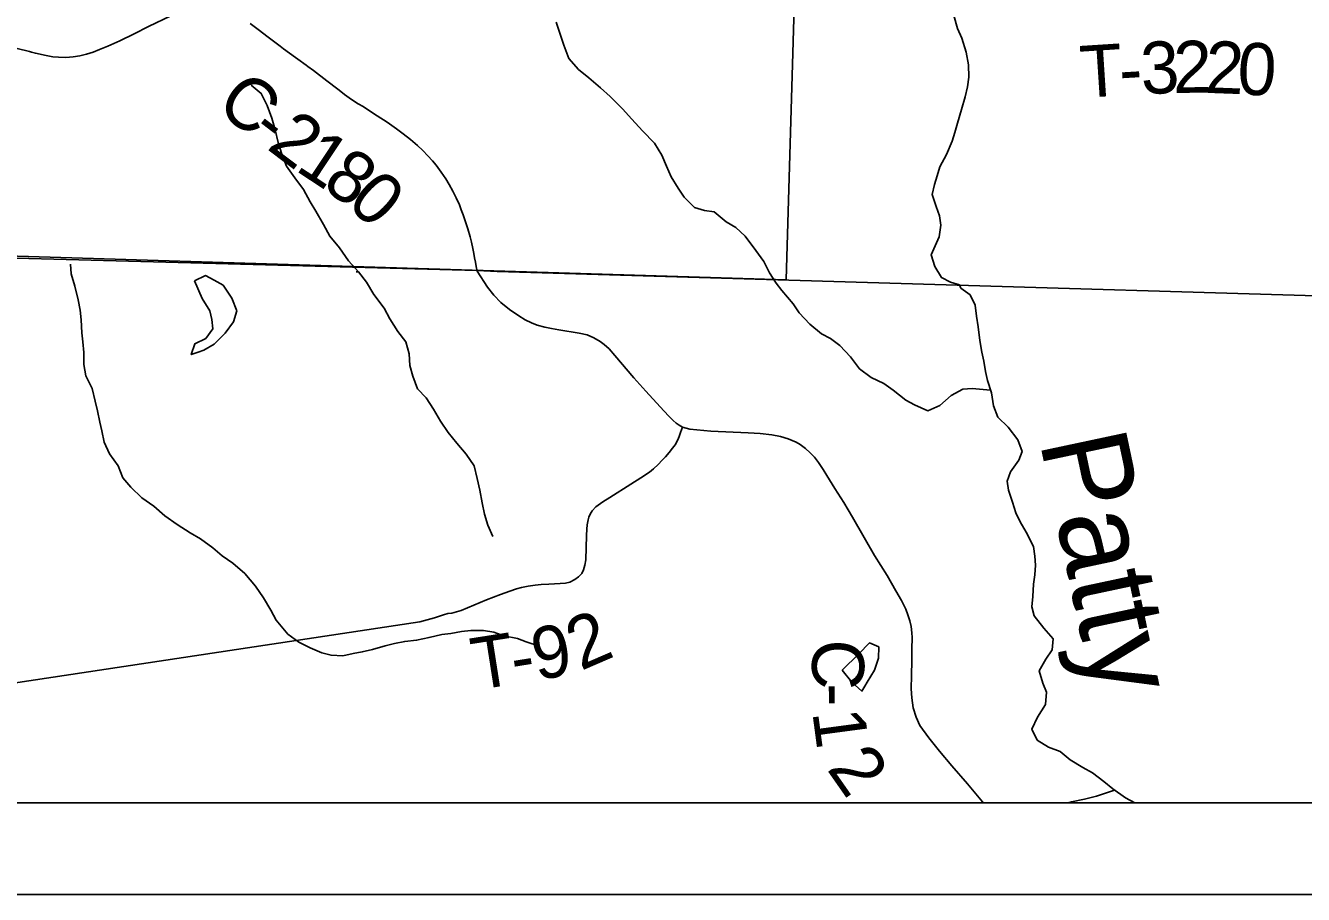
# Model space of a CAD drawing. Extents: x 0 to 34, y 0 to 22.
# Drawn here: x 24.166 to 25.56, y 14 to 14.948 of the extents above; entities that cross this region are included whole.
import ezdxf

# ---------------------------------------------------------------- set-up
doc = ezdxf.new("R2010")
doc.units = 0
for name, color, linetype in [('GM_X_Corporation', 7, 'Continuous'), ('GM_X_County_Road', 7, 'Continuous'), ('GM_X_County_Road_Text', 7, 'Continuous'), ('GM_X_Minor_Lake', 7, 'Continuous'), ('GM_X_Minor_River', 7, 'Continuous'), ('GM_X_Minor_River_Text', 7, 'Continuous'), ('GM_X_Township_Road', 7, 'Continuous'), ('GM_X_Township_Road_Text', 7, 'Continuous'), ('SH_Data', 7, 'Continuous')]:
    doc.layers.add(name, color=color, linetype=linetype)

msp = doc.modelspace()

# ---------------------------------------------------------------- linework, layer by layer
at = {"layer": 'GM_X_Corporation'}
for points in [[(30.3167, 20.9), (23.5167, 20.9), (23.5167, 14.7114), (24.6586, 14.6808), (24.6805, 14.6799), (26.0522, 14.6391), (26.4447, 14.6283), (26.4468, 14.6272), (26.4498, 14.6263), (26.4544, 14.6257), (26.5226, 14.6248), (26.5325, 14.6248), (26.5616, 14.6241), (26.5684, 14.624), (26.5727, 14.624), (26.5813, 14.6239), (26.5991, 14.6234), (26.6128, 14.6229), (26.6208, 14.6225), (26.6337, 14.622), (26.643, 14.6216), (26.6535, 14.621), (27.01, 14.6164)], [(23.5167, 20.7862), (23.5167, 14.7114), (24.6586, 14.6808), (24.6805, 14.6799), (26.0522, 14.6391), (26.4447, 14.6283), (26.4468, 14.6272), (26.4498, 14.6263), (26.4544, 14.6257), (26.5226, 14.6248), (26.5325, 14.6248), (26.5616, 14.6241), (26.5684, 14.624), (26.5727, 14.624), (26.5813, 14.6239), (26.5991, 14.6234), (26.6128, 14.6229), (26.6208, 14.6225), (26.6337, 14.622), (26.643, 14.6216), (26.6535, 14.621), (27.01, 14.6164)], [(27.01, 14.6164), (26.6535, 14.621), (26.643, 14.6216), (26.6337, 14.622), (26.6208, 14.6225), (26.6128, 14.6229), (26.5991, 14.6234), (26.5813, 14.6239), (26.5727, 14.624), (26.5684, 14.624), (26.5616, 14.6241), (26.5325, 14.6248), (26.5226, 14.6248), (26.4544, 14.6257), (26.4498, 14.6263), (26.4468, 14.6272), (26.4447, 14.6283), (26.0522, 14.6391), (24.6805, 14.6799), (24.6586, 14.6808), (23.5167, 14.7114), (23.5167, 14.1), (30.3167, 14.1)]]:
    msp.add_lwpolyline(points, dxfattribs=at)
for points in [[(23.9985, 15.7225), (25.0261, 15.6992), (24.9959, 14.6707), (24.0266, 14.7005), (23.9793, 14.7018)], [(23.5167, 14.7114), (23.5167, 14.1), (26.0358, 14.1), (26.0365, 14.1243), (26.0522, 14.6391), (24.6805, 14.6799), (24.6586, 14.6808)]]:
    msp.add_lwpolyline(points, close=True, dxfattribs=at)
at = {"layer": 'GM_X_County_Road'}
for points in [[(24.3244, 14.9589), (24.2998, 14.9471), (24.2842, 14.9394), (24.2686, 14.9317), (24.2556, 14.9258), (24.2464, 14.922), (24.2394, 14.9194), (24.2323, 14.9172), (24.2251, 14.9154), (24.2177, 14.9141), (24.2097, 14.9135), (24.2016, 14.9136), (24.1955, 14.9143), (24.1881, 14.9156), (24.1766, 14.9181), (24.1724, 14.9192), (24.17, 14.9198), (24.1567, 14.9231)], [(24.6588, 14.6802), (24.6576, 14.6852), (24.6567, 14.69), (24.6557, 14.6948), (24.6549, 14.6996), (24.6539, 14.7051), (24.6525, 14.7118), (24.651, 14.7178), (24.6486, 14.7264), (24.6434, 14.7417), (24.6413, 14.7473), (24.6392, 14.7525), (24.6356, 14.7604), (24.632, 14.7676), (24.6281, 14.7747), (24.6243, 14.7811), (24.6194, 14.7883), (24.6138, 14.7958), (24.6098, 14.8005), (24.6048, 14.806), (24.5993, 14.8118), (24.5934, 14.8174), (24.5858, 14.8238), (24.578, 14.83), (24.5706, 14.8356), (24.5605, 14.8427), (24.5496, 14.8498), (24.5388, 14.8568), (24.5341, 14.8598), (24.5288, 14.863), (24.5215, 14.8677), (24.5139, 14.8731), (24.508, 14.8776), (24.5065, 14.8788), (24.4947, 14.8879), (24.4799, 14.8992), (24.474, 14.9037), (24.4719, 14.9051), (24.4628, 14.9116), (24.4603, 14.9133), (24.4474, 14.9229), (24.4435, 14.9259), (24.438, 14.93), (24.4306, 14.9356), (24.4197, 14.9439), (24.4108, 14.9505)], [(24.6588, 14.6802), (24.6698, 14.6627), (24.6769, 14.6541), (24.6845, 14.6462), (24.6938, 14.6385), (24.7041, 14.6315), (24.7112, 14.627), (24.7179, 14.6239), (24.7241, 14.6214), (24.7326, 14.6191), (24.7397, 14.6177), (24.7478, 14.6163), (24.77, 14.6125), (24.7786, 14.6106), (24.786, 14.6076), (24.7927, 14.6036), (24.7973, 14.6002), (24.8026, 14.5956), (24.8089, 14.5883), (24.8296, 14.5639), (24.8426, 14.5493), (24.8585, 14.532), (24.8674, 14.5223), (24.8726, 14.5172), (24.8759, 14.5143), (24.8791, 14.512), (24.8826, 14.5101), (24.8909, 14.5079), (24.8985, 14.507), (24.9135, 14.5057), (24.9543, 14.5037), (24.9608, 14.5034), (24.9676, 14.503), (24.9801, 14.5017), (24.9897, 14.4998), (24.9981, 14.4971), (25.0066, 14.4937), (25.0112, 14.491), (25.0171, 14.4866), (25.0222, 14.4821), (25.0269, 14.4771), (25.0313, 14.4713), (25.0364, 14.4638), (25.0403, 14.4573), (25.0491, 14.4431), (25.0587, 14.4276), (25.0682, 14.4116), (25.081, 14.3894), (25.0924, 14.37), (25.106, 14.3482), (25.1156, 14.3314), (25.1217, 14.3207), (25.1263, 14.3112), (25.1286, 14.3053), (25.1307, 14.2985), (25.1321, 14.2923), (25.133, 14.2854), (25.1332, 14.2803), (25.133, 14.2678), (25.1329, 14.2552), (25.1325, 14.2389), (25.1322, 14.2245), (25.1329, 14.2146), (25.1346, 14.2035), (25.1378, 14.1934), (25.1419, 14.1842), (25.1514, 14.1708), (25.1631, 14.1563), (25.1767, 14.1402), (25.1936, 14.1208), (25.2102, 14.1009), (25.211, 14.1)]]:
    msp.add_lwpolyline(points, dxfattribs=at)
at = {"layer": 'GM_X_Minor_Lake'}
for points in [[(24.354, 14.5918), (24.3603, 14.5939), (24.3716, 14.6004), (24.3836, 14.6126), (24.3929, 14.6248), (24.3963, 14.637), (24.3909, 14.6506), (24.3813, 14.6649), (24.3718, 14.6705), (24.3623, 14.6754), (24.3503, 14.6696)], [(24.3503, 14.6696), (24.3587, 14.6503), (24.3668, 14.6371), (24.3691, 14.6273), (24.3703, 14.6174), (24.3624, 14.6068), (24.3504, 14.601), (24.3467, 14.5892), (24.354, 14.5918)], [(25.0816, 14.2274), (25.0841, 14.2318), (25.0924, 14.2447), (25.0965, 14.258), (25.0969, 14.2701), (25.0867, 14.2746), (25.0753, 14.2625), (25.0568, 14.2446)], [(25.0568, 14.2446), (25.0675, 14.2317), (25.0785, 14.2219), (25.0816, 14.2274)]]:
    msp.add_lwpolyline(points, dxfattribs=at)
at = {"layer": 'GM_X_Minor_River'}
for points in [[(24.7447, 14.9521), (24.749, 14.94), (24.7533, 14.9268), (24.7587, 14.9124), (24.7694, 14.9004), (24.7804, 14.8913), (24.7934, 14.8804), (24.8037, 14.8707), (24.8171, 14.8575), (24.8274, 14.8462), (24.8392, 14.8334), (24.8522, 14.8198), (24.8603, 14.807), (24.8653, 14.7949), (24.8703, 14.7831), (24.878, 14.7707), (24.8845, 14.7609), (24.8959, 14.7496), (24.9066, 14.7466), (24.9172, 14.7448), (24.9305, 14.7339), (24.9408, 14.7279), (24.9511, 14.7185)], [(25.1865, 14.6618), (25.185, 14.6654), (25.1752, 14.6683), (25.1653, 14.6732), (25.158, 14.6853), (25.1541, 14.6981), (25.1586, 14.7077), (25.163, 14.7176), (25.1645, 14.7305), (25.1633, 14.7407), (25.1594, 14.7509), (25.1551, 14.7638), (25.1577, 14.7748), (25.1607, 14.7843), (25.1636, 14.7942), (25.1707, 14.8076), (25.1771, 14.822), (25.18, 14.8316), (25.183, 14.8418), (25.1871, 14.8567), (25.1911, 14.8704), (25.1937, 14.8814), (25.1952, 14.892), (25.1947, 14.9053), (25.1923, 14.9193), (25.1877, 14.9345), (25.183, 14.945), (25.1788, 14.9594)], [(24.5265, 14.6794), (24.5292, 14.6794), (24.5184, 14.6914), (24.5084, 14.7057), (24.4977, 14.7185), (24.4908, 14.7313), (24.4827, 14.7457), (24.4765, 14.7558), (24.4692, 14.7694), (24.4596, 14.7822), (24.4507, 14.795), (24.4453, 14.8078), (24.4414, 14.8207), (24.4382, 14.8343), (24.4347, 14.8471), (24.4296, 14.8611), (24.423, 14.8743), (24.412, 14.8833)], [(24.9511, 14.7185), (24.9626, 14.7027), (24.9714, 14.6906), (24.9776, 14.6785), (24.9851, 14.6671)], [(24.2147, 14.688), (24.2155, 14.6772), (24.2194, 14.6639), (24.2233, 14.6488), (24.2253, 14.6378), (24.2265, 14.6272), (24.2273, 14.6128), (24.2282, 14.603), (24.2294, 14.5916), (24.2295, 14.5784), (24.2315, 14.5659), (24.2384, 14.5523), (24.2419, 14.5383), (24.2443, 14.5277), (24.247, 14.5156), (24.249, 14.5058), (24.2517, 14.4936), (24.2575, 14.4808), (24.2667, 14.4676), (24.2721, 14.4548), (24.2805, 14.4446), (24.2927, 14.433), (24.3056, 14.4236), (24.3178, 14.4131), (24.3312, 14.4037), (24.3456, 14.3947), (24.3566, 14.388), (24.3703, 14.3783), (24.3802, 14.3696), (24.392, 14.3614), (24.405, 14.3501), (24.4168, 14.3366), (24.4256, 14.3237), (24.4333, 14.3102), (24.4394, 14.2992), (24.4521, 14.2842), (24.4642, 14.2755), (24.4764, 14.2692), (24.4893, 14.2636), (24.4992, 14.261), (24.512, 14.2604), (24.5234, 14.2628), (24.5332, 14.2647), (24.5445, 14.2675), (24.5581, 14.2714), (24.5683, 14.2737), (24.5796, 14.2761), (24.5925, 14.2774), (24.6061, 14.2805), (24.6201, 14.2836), (24.6299, 14.2849), (24.6416, 14.2869), (24.6518, 14.2881), (24.6654, 14.2882), (24.6769, 14.2863)], [(24.5292, 14.6794), (24.538, 14.6681), (24.546, 14.6549), (24.5571, 14.6398), (24.5633, 14.6281), (24.5721, 14.6145), (24.5809, 14.6032), (24.5844, 14.59), (24.5852, 14.5771), (24.5883, 14.5658), (24.5937, 14.5518), (24.6029, 14.542), (24.6109, 14.5296), (24.6186, 14.5164), (24.627, 14.5043), (24.6366, 14.4926), (24.6465, 14.4806), (24.6553, 14.4678), (24.6588, 14.4538), (24.6616, 14.4413), (24.664, 14.4273), (24.6667, 14.4152), (24.6702, 14.4031), (24.6759, 14.3908)], [(25.2189, 14.5505), (25.1987, 14.5521), (25.1888, 14.5514), (25.176, 14.5445), (25.1635, 14.5338), (25.1503, 14.5277), (25.1359, 14.5345), (25.1264, 14.5394), (25.1127, 14.5503), (25.1025, 14.5575), (25.0888, 14.5643), (25.0759, 14.5737), (25.066, 14.5866), (25.0543, 14.599), (25.0444, 14.6066), (25.0345, 14.6119), (25.0216, 14.6224), (25.0102, 14.6349), (25.0034, 14.6447), (24.9912, 14.6591), (24.9851, 14.6671)], [(25.2873, 14.2791), (25.2771, 14.2905), (25.2664, 14.3041), (25.2641, 14.3139), (25.2652, 14.3253), (25.2659, 14.3386), (25.2674, 14.3488), (25.2678, 14.3594), (25.2674, 14.3693), (25.2658, 14.3799), (25.2578, 14.3954), (25.2513, 14.4068), (25.2464, 14.4166), (25.243, 14.4283), (25.2384, 14.4412), (25.2372, 14.4511), (25.2406, 14.4613), (25.2496, 14.4738), (25.2534, 14.4833), (25.2488, 14.4962), (25.2382, 14.5098), (25.2268, 14.5208), (25.2222, 14.5333), (25.2199, 14.5473), (25.2157, 14.5609), (25.2134, 14.5708), (25.2114, 14.5821), (25.2095, 14.592), (25.2072, 14.6045), (25.2053, 14.6193), (25.2037, 14.631), (25.2022, 14.6431), (25.1965, 14.6545), (25.1865, 14.6618)], [(24.7265, 14.271), (24.7122, 14.2756), (24.7027, 14.2794), (24.6879, 14.2824), (24.6769, 14.2863)], [(25.3766, 14.1), (25.3764, 14.1001), (25.3662, 14.1054), (25.3525, 14.1152), (25.3427, 14.1231), (25.3302, 14.1329), (25.3195, 14.1386), (25.3059, 14.1469), (25.2949, 14.1559), (25.282, 14.1608), (25.2698, 14.1684), (25.2641, 14.1805), (25.2702, 14.1934), (25.2788, 14.2074), (25.2799, 14.2207), (25.2761, 14.2306), (25.2719, 14.2442), (25.2791, 14.2567), (25.2862, 14.267), (25.2873, 14.2791)], [(25.3543, 14.1139), (25.3344, 14.1072), (25.3215, 14.1041), (25.3072, 14.101), (25.3036, 14.1)]]:
    msp.add_lwpolyline(points, dxfattribs=at)
at = {"layer": 'GM_X_Township_Road'}
for points in [[(24.8826, 14.5101), (24.8806, 14.5041), (24.8792, 14.4999), (24.8777, 14.4962), (24.8747, 14.4908), (24.8719, 14.487), (24.8683, 14.4822), (24.8643, 14.4777), (24.8607, 14.4739), (24.856, 14.4691), (24.8509, 14.4646), (24.8466, 14.4609), (24.8373, 14.4546), (24.8265, 14.4476), (24.8034, 14.4333), (24.7957, 14.4284), (24.7881, 14.4229), (24.7841, 14.4187), (24.782, 14.4152), (24.7806, 14.4119), (24.7796, 14.4087), (24.7787, 14.4034), (24.7784, 14.3988), (24.7781, 14.3919), (24.7773, 14.3651), (24.7761, 14.3593), (24.7747, 14.3543), (24.7727, 14.3504), (24.7693, 14.3468), (24.7652, 14.3436), (24.7597, 14.3409), (24.7552, 14.3399), (24.7493, 14.3393), (24.7368, 14.3386), (24.7286, 14.3382), (24.7219, 14.3374), (24.7143, 14.3366), (24.7072, 14.3351), (24.7015, 14.3335), (24.6944, 14.331), (24.6841, 14.3273), (24.6687, 14.3215), (24.6549, 14.3156), (24.6413, 14.3099), (24.6311, 14.307), (24.6268, 14.3065), (24.6218, 14.305)], [(24.6218, 14.305), (24.6119, 14.3019), (24.596, 14.2977), (24.1113, 14.2245)]]:
    msp.add_lwpolyline(points, dxfattribs=at)
at = {"layer": 'SH_Data'}
for points in [[(23.4167, 21), (30.4167, 21), (30.4167, 14), (23.4167, 14)], [(23.5167, 20.9), (30.3167, 20.9), (30.3167, 14.1), (23.5167, 14.1)]]:
    msp.add_lwpolyline(points, close=True, dxfattribs=at)

# ---------------------------------------------------------------- texts
at = {"layer": 'GM_X_County_Road_Text'}
for s, rotation, p in [('C', 322.3167, (24.3718, 14.8575)), ('-', 322.4228, (24.4088, 14.8289)), ('2', 322.977, (24.4278, 14.8144)), ('1', 326.4146, (24.4588, 14.7911)), ('8', 325.135, (24.4877, 14.772)), ('0', 317.3189, (24.5148, 14.7532)), ('C', 268.4699, (25.0249, 14.279)), ('-', 270.0924, (25.0237, 14.2306)), ('1', 277.6209, (25.0243, 14.1991)), ('2', 304.9441, (25.0395, 14.1371))]:
    msp.add_text(s, height=0.0568, rotation=rotation, dxfattribs=at).set_placement(p)
at = {"layer": 'GM_X_Minor_River_Text'}
msp.add_text('Patty', height=0.09469, rotation=282.0053, dxfattribs=at).set_placement((25.2723, 14.4945))
at = {"layer": 'GM_X_Township_Road_Text'}
for s, rotation, p in [('T', 3.6902, (25.3183, 14.8692)), ('3', 2.3894, (25.3837, 14.8733)), ('2', 0.1717, (25.4181, 14.8748)), ('2', 357.8684, (25.4524, 14.8749)), ('0', 356.7587, (25.4871, 14.8736)), ('-', 3.4054, (25.3606, 14.8719)), ('9', 10.0796, (24.7235, 14.2334)), ('2', 23.4143, (24.7717, 14.2437)), ('T', 8.9156, (24.6572, 14.2229)), ('-', 9.1284, (24.6994, 14.2296))]:
    msp.add_text(s, height=0.0568, rotation=rotation, dxfattribs=at).set_placement(p)

doc.saveas('drawing.dxf')
